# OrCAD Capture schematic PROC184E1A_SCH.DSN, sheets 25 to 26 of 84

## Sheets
25 24. SOC ANALOG POWER 1: size C; title: SOC ANALOG POWER 1; company: TEXAS INSTRUMENTS INCORPORATED; note: PROC184_SCH
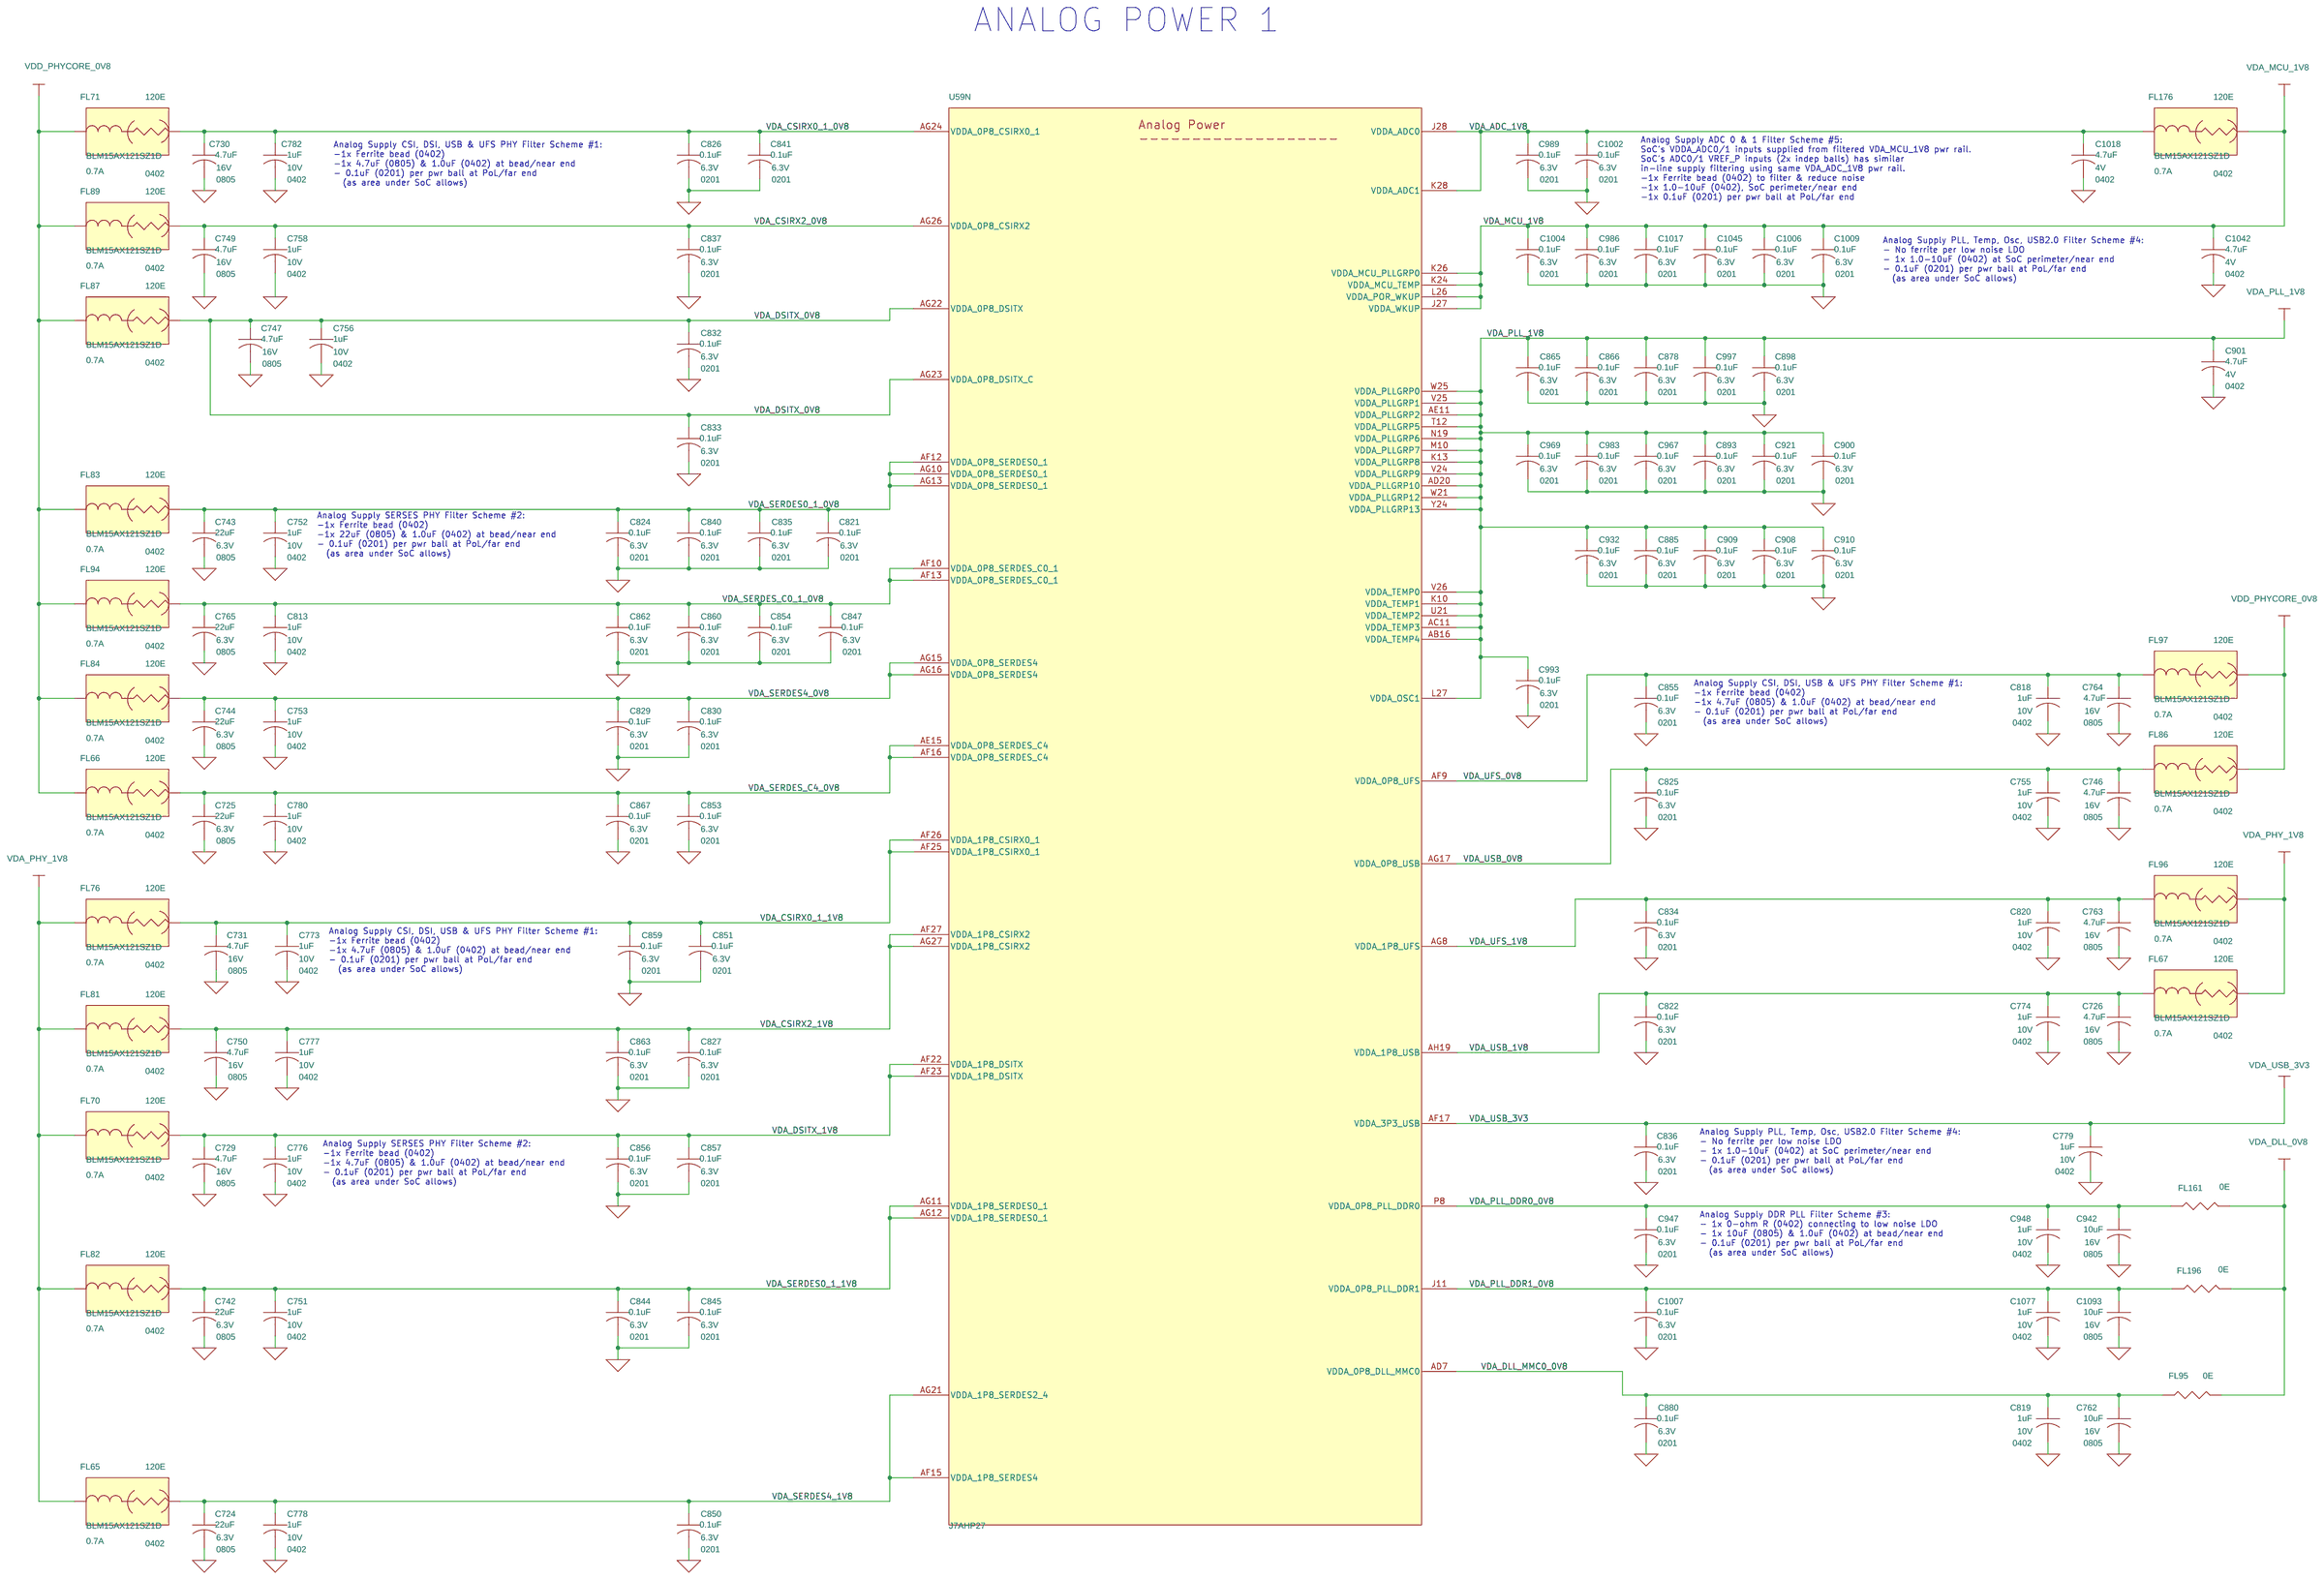
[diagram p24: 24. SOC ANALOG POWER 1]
26 25. SOC IO & SUPPORT POWER 2: size C; title: SOC DIGITAL IO & SUPPORT POWER 2; company: TEXAS INSTRUMENTS INCORPORATED; note: PROC184_SCH
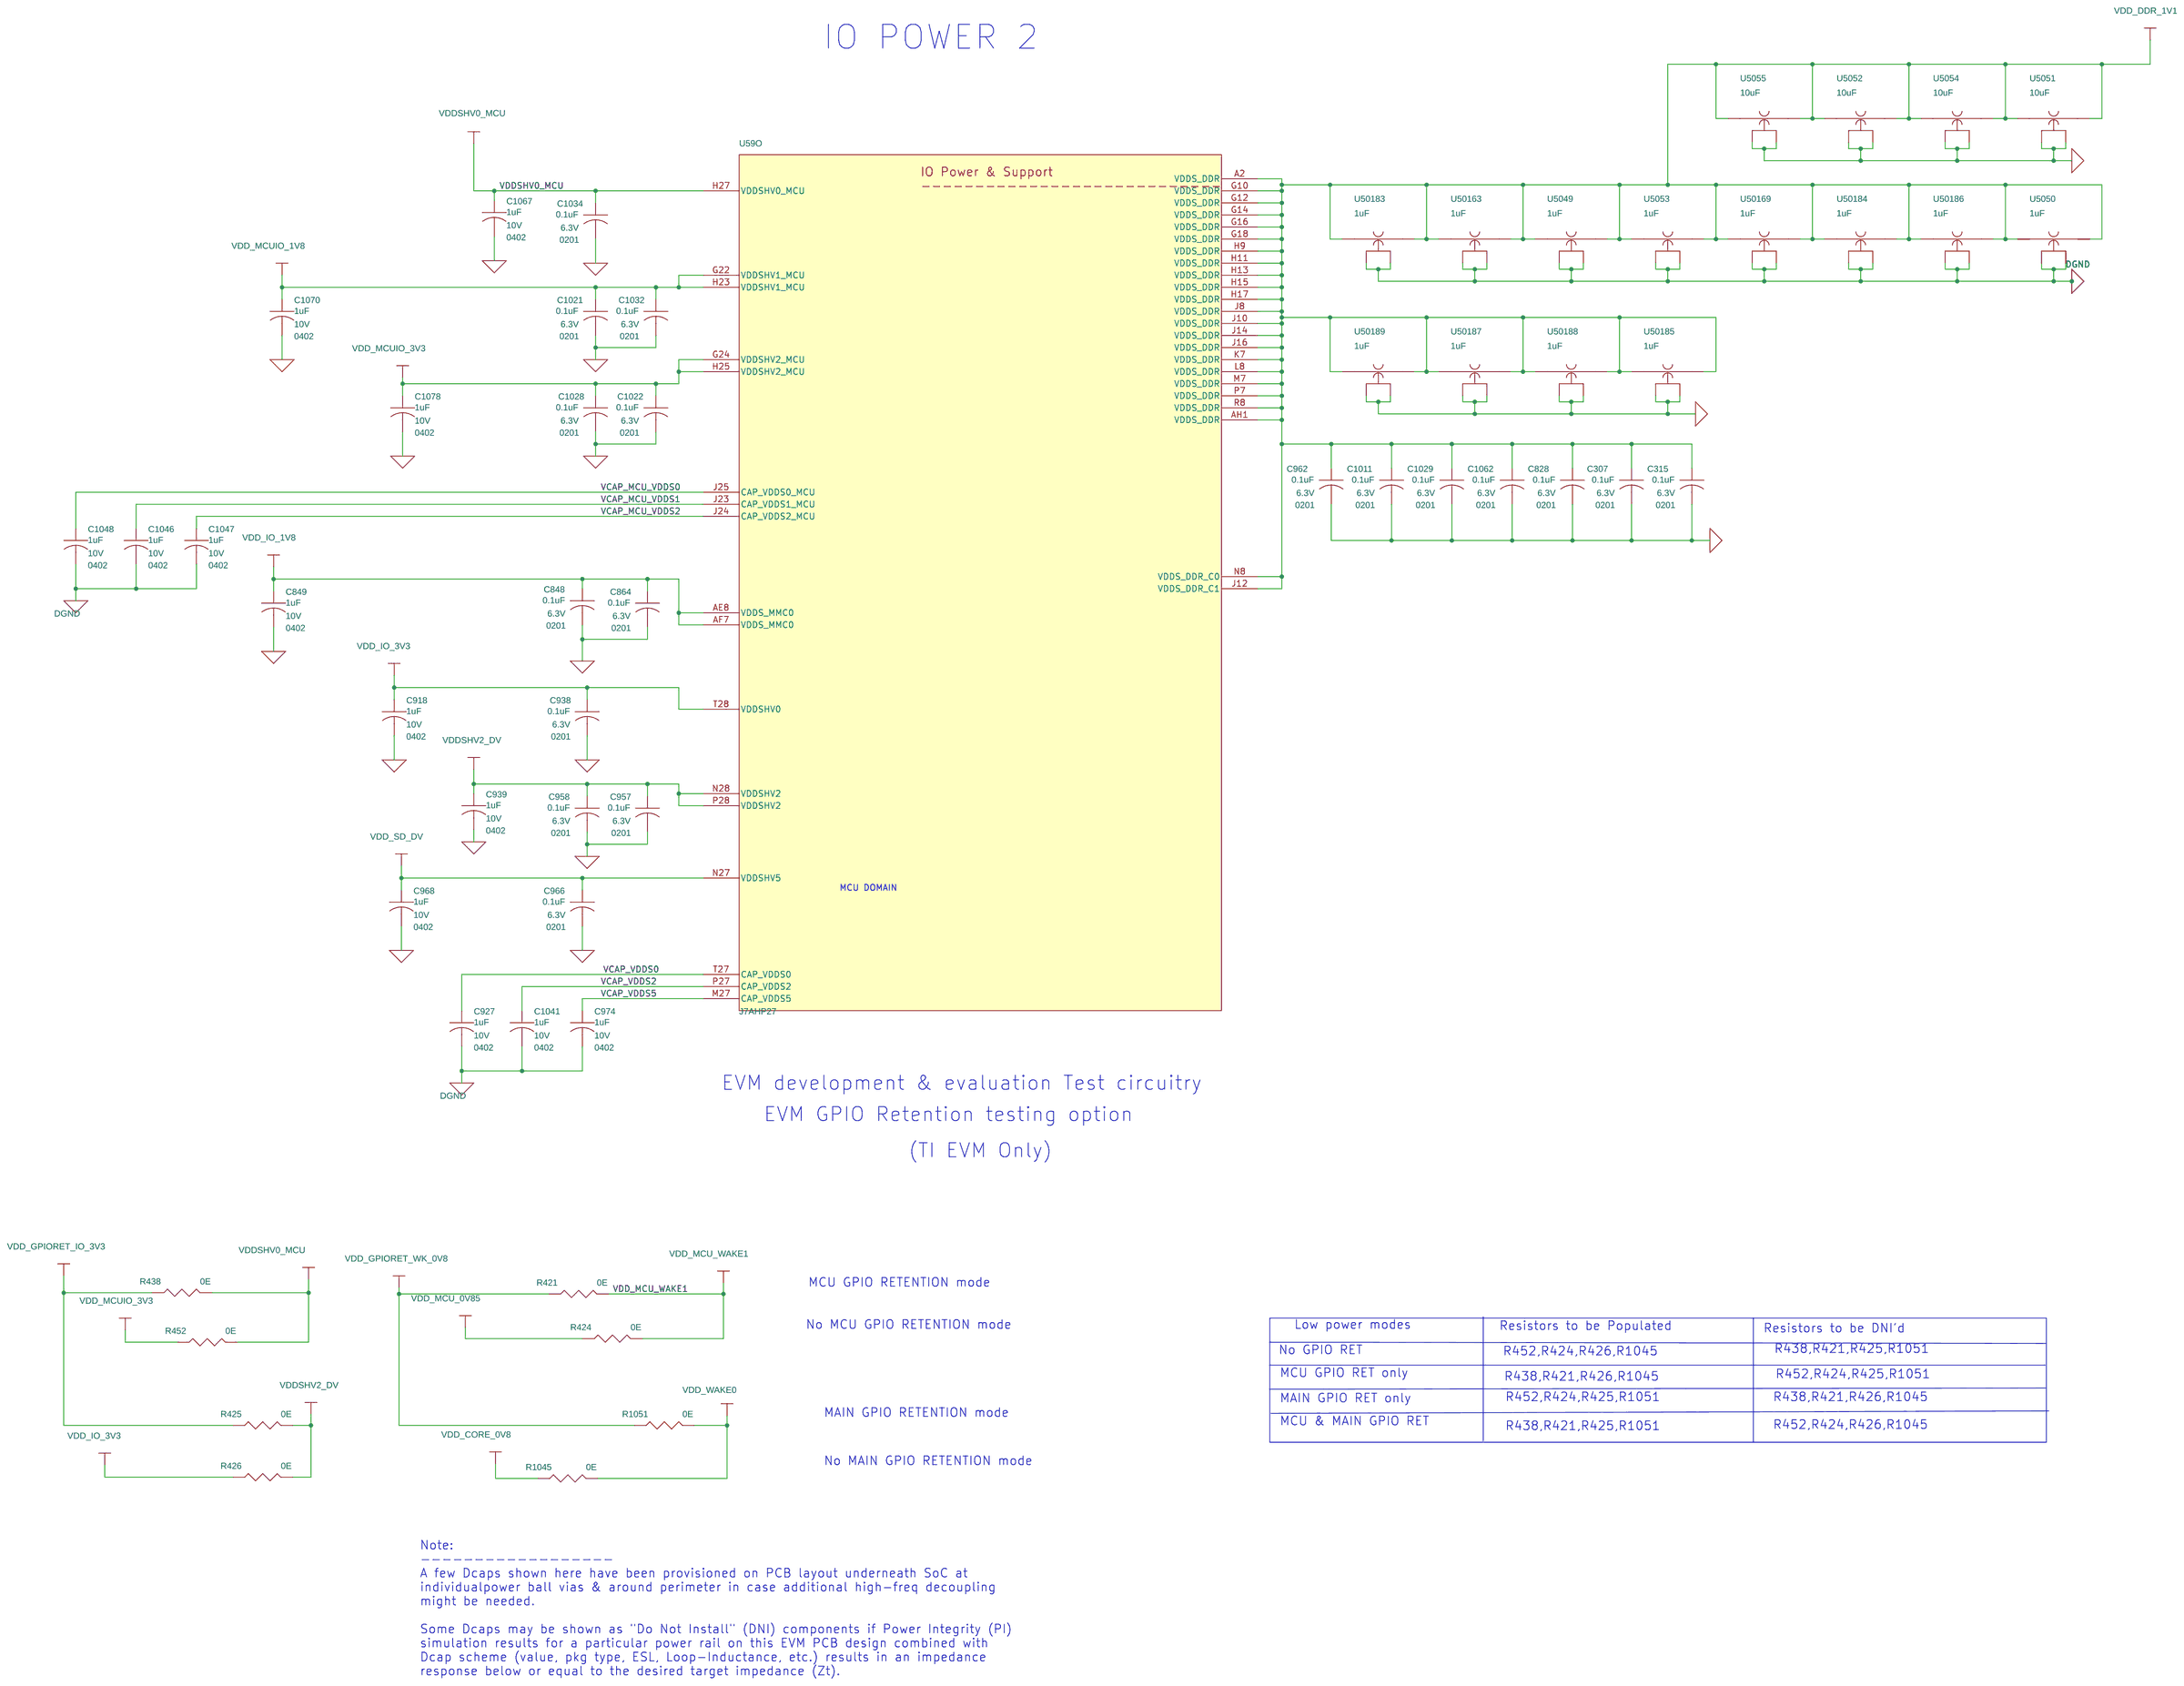
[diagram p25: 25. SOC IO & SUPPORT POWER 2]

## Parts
sheet 15. SOC EMIF1 & LPDDR4
U59  J7AHP27  [BGASKT-33X33-1063-P8MM]  (sections A,B,C,D,E,F,G,H,I,J,K,L,M,N,O,P,Q,R,S,T,U,V,W)
sheet 24. SOC ANALOG POWER 1
C724  22uF  [CAP0805_1-25]
C725  22uF  [CAP0805_1-25]
C726  4.7uF  [CAP0805_1-5]
C729  4.7uF  [CAP0805_1-5]
C730  4.7uF  [CAP0805_1-5]
C731  4.7uF  [CAP0805_1-5]
C742  22uF  [CAP0805_1-25]
C743  22uF  [CAP0805_1-25]
C744  22uF  [CAP0805_1-25]
C746  4.7uF  [CAP0805_1-5]
C747  4.7uF  [CAP0805_1-5]
C749  4.7uF  [CAP0805_1-5]
C750  4.7uF  [CAP0805_1-5]
C751  1uF  [CAP0402_0-75]
C752  1uF  [CAP0402_0-75]
C753  1uF  [CAP0402_0-75]
C755  1uF  [CAP0402_0-75]
C756  1uF  [CAP0402_0-75]
C758  1uF  [CAP0402_0-75]
C762  10uF  [CAP0805_1-5]
C763  4.7uF  [CAP0805_1-5]
C764  4.7uF  [CAP0805_1-5]
C765  22uF  [CAP0805_1-25]
C773  1uF  [CAP0402_0-75]
C774  1uF  [CAP0402_0-75]
C776  1uF  [CAP0402_0-75]
C777  1uF  [CAP0402_0-75]
C778  1uF  [CAP0402_0-75]
C779  1uF  [CAP0402_0-75]
C780  1uF  [CAP0402_0-75]
C782  1uF  [CAP0402_0-75]
C813  1uF  [CAP0402_0-75]
C818  1uF  [CAP0402_0-75]
C819  1uF  [CAP0402_0-75]
C820  1uF  [CAP0402_0-75]
C821  0.1uF  [CAP0201_0-5]
C822  0.1uF  [CAP0201_0-5]
C824  0.1uF  [CAP0201_0-5]
C825  0.1uF  [CAP0201_0-5]
C826  0.1uF  [CAP0201_0-5]
C827  0.1uF  [CAP0201_0-5]
C829  0.1uF  [CAP0201_0-5]
C830  0.1uF  [CAP0201_0-5]
C832  0.1uF  [CAP0201_0-5]
C833  0.1uF  [CAP0201_0-5]
C834  0.1uF  [CAP0201_0-5]
C835  0.1uF  [CAP0201_0-5]
C836  0.1uF  [CAP0201_0-5]
C837  0.1uF  [CAP0201_0-5]
C840  0.1uF  [CAP0201_0-5]
C841  0.1uF  [CAP0201_0-5]
C844  0.1uF  [CAP0201_0-5]
C845  0.1uF  [CAP0201_0-5]
C847  0.1uF  [CAP0201_0-5]
C850  0.1uF  [CAP0201_0-5]
C851  0.1uF  [CAP0201_0-5]
C853  0.1uF  [CAP0201_0-5]
C854  0.1uF  [CAP0201_0-5]
C855  0.1uF  [CAP0201_0-5]
C856  0.1uF  [CAP0201_0-5]
C857  0.1uF  [CAP0201_0-5]
C859  0.1uF  [CAP0201_0-5]
C860  0.1uF  [CAP0201_0-5]
C862  0.1uF  [CAP0201_0-5]
C863  0.1uF  [CAP0201_0-5]
C865  0.1uF  [CAP0201_0-5]
C866  0.1uF  [CAP0201_0-5]
C867  0.1uF  [CAP0201_0-5]
C878  0.1uF  [CAP0201_0-5]
C880  0.1uF  [CAP0201_0-5]
C885  0.1uF  [CAP0201_0-5]
C893  0.1uF  [CAP0201_0-5]
C898  0.1uF  [CAP0201_0-5]
C900  0.1uF  [CAP0201_0-5]
C901  4.7uF  [CAP0402_0-75]
C908  0.1uF  [CAP0201_0-5]
C909  0.1uF  [CAP0201_0-5]
C910  0.1uF  [CAP0201_0-5]
C921  0.1uF  [CAP0201_0-5]
C932  0.1uF  [CAP0201_0-5]
C942  10uF  [CAP0805_1-5]
C947  0.1uF  [CAP0201_0-5]
C948  1uF  [CAP0402_0-75]
C967  0.1uF  [CAP0201_0-5]
C969  0.1uF  [CAP0201_0-5]
C983  0.1uF  [CAP0201_0-5]
C986  0.1uF  [CAP0201_0-5]
C989  0.1uF  [CAP0201_0-5]
C993  0.1uF  [CAP0201_0-5]
C997  0.1uF  [CAP0201_0-5]
C1002  0.1uF  [CAP0201_0-5]
C1004  0.1uF  [CAP0201_0-5]
C1006  0.1uF  [CAP0201_0-5]
C1007  0.1uF  [CAP0201_0-5]
C1009  0.1uF  [CAP0201_0-5]
C1017  0.1uF  [CAP0201_0-5]
C1018  4.7uF  [CAP0402_0-75]
C1042  4.7uF  [CAP0402_0-75]
C1045  0.1uF  [CAP0201_0-5]
C1077  1uF  [CAP0402_0-75]
C1093  10uF  [CAP0805_1-5]
FL65  120E  [EMIFIL_BLM15A_0402_0-6]
FL66  120E  [EMIFIL_BLM15A_0402_0-6]
FL67  120E  [EMIFIL_BLM15A_0402_0-6]
FL70  120E  [EMIFIL_BLM15A_0402_0-6]
FL71  120E  [EMIFIL_BLM15A_0402_0-6]
FL76  120E  [EMIFIL_BLM15A_0402_0-6]
FL81  120E  [EMIFIL_BLM15A_0402_0-6]
FL82  120E  [EMIFIL_BLM15A_0402_0-6]
FL83  120E  [EMIFIL_BLM15A_0402_0-6]
FL84  120E  [EMIFIL_BLM15A_0402_0-6]
FL86  120E  [EMIFIL_BLM15A_0402_0-6]
FL87  120E  [EMIFIL_BLM15A_0402_0-6]
FL89  120E  [EMIFIL_BLM15A_0402_0-6]
FL94  120E  [EMIFIL_BLM15A_0402_0-6]
FL95  0E  [RES0402_0-5]
FL96  120E  [EMIFIL_BLM15A_0402_0-6]
FL97  120E  [EMIFIL_BLM15A_0402_0-6]
FL161  0E  [RES0402_0-5]
FL176  120E  [EMIFIL_BLM15A_0402_0-6]
FL196  0E  [RES0402_0-5]
sheet 25. SOC IO & SUPPORT POWER 2
C307  0.1uF  [CAP0201_0-5]
C315  0.1uF  [CAP0201_0-5]
C828  0.1uF  [CAP0201_0-5]
C848  0.1uF  [CAP0201_0-5]
C849  1uF  [CAP0402_0-75]
C864  0.1uF  [CAP0201_0-5]
C918  1uF  [CAP0402_0-75]
C927  1uF  [CAP0402_0-75]
C938  0.1uF  [CAP0201_0-5]
C939  1uF  [CAP0402_0-75]
C957  0.1uF  [CAP0201_0-5]
C958  0.1uF  [CAP0201_0-5]
C962  0.1uF  [CAP0201_0-5]
C966  0.1uF  [CAP0201_0-5]
C968  1uF  [CAP0402_0-75]
C974  1uF  [CAP0402_0-75]
C1011  0.1uF  [CAP0201_0-5]
C1021  0.1uF  [CAP0201_0-5]
C1022  0.1uF  [CAP0201_0-5]
C1028  0.1uF  [CAP0201_0-5]
C1029  0.1uF  [CAP0201_0-5]
C1032  0.1uF  [CAP0201_0-5]
C1034  0.1uF  [CAP0201_0-5]
C1041  1uF  [CAP0402_0-75]
C1046  1uF  [CAP0402_0-75]
C1047  1uF  [CAP0402_0-75]
C1048  1uF  [CAP0402_0-75]
C1062  0.1uF  [CAP0201_0-5]
C1067  1uF  [CAP0402_0-75]
C1070  1uF  [CAP0402_0-75]
C1078  1uF  [CAP0402_0-75]
R421  0E  [RES0402_0-5]
R424  0E  [RES0402_0-5]
R425  0E  [RES0402_0-5]
R426  0E  [RES0402_0-5]
R438  0E  [RES0402_0-5]
R452  0E  [RES0402_0-5]
R1045  0E  [RES0402_0-5]
R1051  0E  [RES0402_0-5]
U5049  1uF  [EMIFIL_NFM15CC_0402_0-5_TI]
U5050  1uF  [EMIFIL_NFM15CC_0402_0-5_TI]
U5051  10uF  [EMIFIL_NFM18C_0603_0-7_TI]
U5052  10uF  [EMIFIL_NFM18C_0603_0-7_TI]
U5053  1uF  [EMIFIL_NFM15CC_0402_0-5_TI]
U5054  10uF  [EMIFIL_NFM18C_0603_0-7_TI]
U5055  10uF  [EMIFIL_NFM18C_0603_0-7_TI]
U50163  1uF  [EMIFIL_NFM15CC_0402_0-5_TI]
U50169  1uF  [EMIFIL_NFM15CC_0402_0-5_TI]
U50183  1uF  [EMIFIL_NFM15CC_0402_0-5_TI]
U50184  1uF  [EMIFIL_NFM15CC_0402_0-5_TI]
U50185  1uF  [EMIFIL_NFM15CC_0402_0-5_TI]
U50186  1uF  [EMIFIL_NFM15CC_0402_0-5_TI]
U50187  1uF  [EMIFIL_NFM15CC_0402_0-5_TI]
U50188  1uF  [EMIFIL_NFM15CC_0402_0-5_TI]
U50189  1uF  [EMIFIL_NFM15CC_0402_0-5_TI]

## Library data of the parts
U59 = J7AHP27SoC_BGA1063: IC J7AHP27 SoC EVM MICROPROCESSOR BGA1063; Chkd/date: PRADEEP/181223; Crtd /date: TAMILARASU/111223; Custom_Duty: 15%; Customs_HS_Code: 85423100; Distributor_name: NA; Distributor_part_number: NA; Footprint Path: Y:\MIS_DATABASE\Library\ALTIUM_TOOL\PCB_FOOTPRINTS\Altium_Footprint_Lib.PcbLib; Height: 3.30MM; Library Path: Y:\MIS_DATABASE\Library\ALTIUM_TOOL\SCHEMATICS_PARTS\MS_MICROPROCESSOR_Library.schlib; Mfr_name: NA; Mistral Part No: 141223120002; Package: BGA1063; Part_type: ICS\DIGITAL\MICROPROCESSOR; Project: J7AHP27_V08 SOC; RoHS: NA; Temperature: NA; Tolerance: NA; Voltage: NA; Wattage: NA; Weight: NA; Datasheet: Y:\MIS_DATABASE\DATASHEETS\ICS\DIGITAL\MICROCONTROLLER\J7AHP27.PDF
C724 C725 C742-C744 C765 = CAP: CAP CERAMIC 22uF 6.3V 20% X7T AUTO 0805; Automotive Alternate_mfr_name: TDK; Automotive Alternate_mfr_part_number: CGA4J1X7T0J226M; Chkd/date: MANIRAJA/261018; Crtd /date: ALVY/251018; Custom_Duty: 15%; Customs_HS_Code: 85322990; Distributor_name: MOUSER; Distributor_part_number: 81-GCM21BD70J226ME6L; Footprint Path: Y:\MIS_DATABASE\Library\ALTIUM_TOOL\PCB_FOOTPRINTS\Altium_Footprint_Lib.PcbLib; Height: 1.25MM; Library Path: Y:\MIS_DATABASE\Library\ALTIUM_TOOL\SCHEMATICS_PARTS\MS_DISCRETE_Library.schlib; Manufacturer: MURATA; Mfr_name: MURATA; Mfr_part_number: GCM21BD70J226ME36L; Mistral Part No: 120018100065-R; Package: 0805; Part_type: CAPACITORS\CERAMIC; Project: TI_J7ES_EVM_SOM; RoHS: RoHS; Temperature: -55°C+125°C; Tolerance: 20%; Voltage: 6.3V; Wattage: NA; Weight: NA; Datasheet: Y:\MIS_DATABASE\DATASHEETS\CAPACITORS\GCM-SERIES.PDF
C726 C729-C731 C746 C747 C749 C750 C763 C764 = CAP: CAP CERAMIC 4.7uF 16V 10% X7R AUTO 0805; Chkd/date: MANIRAJA/011018; Crtd /date: MANIRAJA/011018; Custom_Duty: 15%; Customs_HS_Code: 85322990; Distributor_name: DIGIKEY; Distributor_part_number: 490-14532-1-ND; Footprint Path: Y:\MIS_DATABASE\Library\ALTIUM_TOOL\PCB_FOOTPRINTS\Altium_Footprint_Lib.PcbLib; Footprint Ref: CAP0805_1-25; Height: 1.40MM; Library Path: Y:\MIS_DATABASE\Library\ALTIUM_TOOL\SCHEMATICS_PARTS\MS_DISCRETE_Library.schlib; Manufacturer: MURATA; Mfr_name: MURATA; Mfr_part_number: GCM21BR71C475KA73K; Mistral Part No: 120018100002-R; Package: 0805; Part_type: CAPACITORS\CERAMIC; Project: TI_J7_SVB-DUT; RoHS: RoHS; Temperature: -55°C+125°C; Tolerance: 10%; Voltage: 16V; Wattage: NA; Weight: 9.5mg; Datasheet: Y:\MIS_DATABASE\DATASHEETS\CAPACITORS\GCM21BR71C475KA73.PDF
C751-C753 C755 C756 C758 C773 C774 C776-C780 C782 C813 C818-C820 C849 C918 C927 C939 C948 C968 C974 C1041 C1046-C1048 C1067 C1070 C1077 C1078 = CAP: CAP CERAMIC 1uF 10V 10% X7S AUTO 0402; Chkd/date: MANIRAJA/100918; Crtd /date: ALVY/100918; Custom_Duty: 15%; Customs_HS_Code: 85322990; Distributor_name: DIGIKEY; Distributor_part_number: 490-13409-1-ND; Footprint Path: Y:\MIS_DATABASE\Library\ALTIUM_TOOL\PCB_FOOTPRINTS\Altium_Footprint_Lib.PcbLib; Height: 0.70MM; Library Path: Y:\MIS_DATABASE\Library\ALTIUM_TOOL\SCHEMATICS_PARTS\MS_DISCRETE_Library.schlib; Manufacturer: MURATA; Mfr_name: MURATA; Mfr_part_number: GCM155C71A105KE38D; Mistral Part No: 120018090021-R; Package: 0402; Part_type: CAPACITORS\CERAMIC; Project: SMART-M_SCRIPTALK_PB; RoHS: RoHS; Temperature: -55°C+125°C; Tolerance: 10%; Voltage: 10V; Wattage: NA; Weight: 6mg; Datasheet: Y:\MIS_DATABASE\DATASHEETS\CAPACITORS\MURATA-GCM-SER.PDF
C762 C942 C1093 = CAP: CAP CERAMIC 10uF 16V 10% X7S AUTO 0805; Automotive Alternate_mfr_name: TDK; Automotive Alternate_mfr_part_number: CGA4J1X7S1C106K125AC; Chkd/date: MANIRAJA/181120; Crtd /date: ALVY/171120; Custom_Duty: 15%; Customs_HS_Code: 85322990; Direct Alternate_mfr_name: TDK; Direct Alternate_mfr_part_number: C2012X7S1C106K125AC; Distributor_name: DIGIKEY; Distributor_part_number: 490-GCM21BC71C106KE36KTR-ND; Footprint Path: Y:\MIS_DATABASE\Library\ALTIUM_TOOL\PCB_FOOTPRINTS\Altium_Footprint_Lib.PcbLib; Height: 1.45MM; Library Path: Y:\MIS_DATABASE\Library\ALTIUM_TOOL\SCHEMATICS_PARTS\MS_DISCRETE_Library.schlib; Manufacturer: MURATA; Mfr_name: MURATA; Mfr_part_number: GCM21BC71C106KE36K; Mistral Part No: 120020110016-R; Package: 0805; Part_type: CAPACITORS\CERAMIC; Project: J7_CP; RoHS: RoHS; Temperature: -55°C+125°C; Tolerance: 10%; Voltage: 16V; Wattage: NA; Weight: 34mg; Datasheet: Y:\MIS_DATABASE\DATASHEETS\CAPACITORS\MURATA-GCM-SER.PDF
C307 C821 C822 C825-C828 C830 C832-C837 C840 C841 C845 C847 C850 C851 C853-C857 C860 C862 C866 C867 C878 C880 C885 C893 C898 C900 C908-C910 C921 C947 C962 C967 C969 C983 C986 C989 C997 C1002 C1006 C1007 C1009 C1029 C1045 = CAP: CAP CERAMIC 0.1uF 6.3V 10% X7S AUTO 0201; Assembly_Instruction: DNI; Chkd/date: MANIRAJA/011018; Crtd /date: MANIRAJA/011018; Custom_Duty: 15%; Customs_HS_Code: 85322990; Distributor_name: NA; Distributor_part_number: NA; Footprint Path: Y:\MIS_DATABASE\Library\ALTIUM_TOOL\PCB_FOOTPRINTS\Altium_Footprint_Lib.PcbLib; Height: 0.33MM; Library Path: Y:\MIS_DATABASE\Library\ALTIUM_TOOL\SCHEMATICS_PARTS\MS_DISCRETE_Library.schlib; Manufacturer: MURATA; Mfr_name: MURATA; Mfr_part_number: GCM033C70J104KE02D; Mistral Part No: 120018100001-R; Package: 0201; Part_type: CAPACITORS\CERAMIC; Project: TI_J7_SVB-DUT; RoHS: RoHS; Temperature: -55°C+125°C; Tolerance: 10%; Voltage: 6.3V; Wattage: NA; Weight: NA; Datasheet: Y:\MIS_DATABASE\DATASHEETS\CAPACITORS\MURATA-GCM-SER.PDF
C315 C824 C829 C844 C848 C859 C863-C865 C932 C938 C957 C958 C966 C993 C1004 C1011 C1017 C1021 C1022 C1028 C1032 C1034 C1062 = CAP: CAP CERAMIC 0.1uF 6.3V 10% X7S AUTO 0201; Chkd/date: MANIRAJA/011018; Crtd /date: MANIRAJA/011018; Custom_Duty: 15%; Customs_HS_Code: 85322990; Distributor_name: NA; Distributor_part_number: NA; Footprint Path: Y:\MIS_DATABASE\Library\ALTIUM_TOOL\PCB_FOOTPRINTS\Altium_Footprint_Lib.PcbLib; Height: 0.33MM; Library Path: Y:\MIS_DATABASE\Library\ALTIUM_TOOL\SCHEMATICS_PARTS\MS_DISCRETE_Library.schlib; Manufacturer: MURATA; Mfr_name: MURATA; Mfr_part_number: GCM033C70J104KE02D; Mistral Part No: 120018100001-R; Package: 0201; Part_type: CAPACITORS\CERAMIC; Project: TI_J7_SVB-DUT; RoHS: RoHS; Temperature: -55°C+125°C; Tolerance: 10%; Voltage: 6.3V; Wattage: NA; Weight: NA; Datasheet: Y:\MIS_DATABASE\DATASHEETS\CAPACITORS\MURATA-GCM-SER.PDF
C901 C1018 C1042 = CAP: CAP CERAMIC 4.7uF 4V 20% X7T 0402; Chkd/date: PRAVEEN/130922; Crtd /date: PRAVEEN/130922; Custom_Duty: 15%; Customs_HS_Code: 85322990; Distributor_name: NA; Distributor_part_number: NA; Footprint Path: Y:\MIS_DATABASE\Library\ALTIUM_TOOL\PCB_FOOTPRINTS\Altium_Footprint_Lib.PcbLib; Height: 0.70MM; Library Path: Y:\MIS_DATABASE\Library\ALTIUM_TOOL\SCHEMATICS_PARTS\MS_DISCRETE_Library.schlib; Manufacturer: MURATA; Mfr_name: MURATA; Mfr_part_number: GCM155D70G475ME36; Mistral Part No: 120022090013-R; Package: 0402; Part_type: CAPACITORS\CERAMIC; Project: J7AHP_EVM; RoHS: RoHS; Temperature: -55°C+125°C; Tolerance: 20%; Voltage: 4V; Wattage: NA; Weight: 1.6mg; Datasheet: Y:\MIS_DATABASE\DATASHEETS\CAPACITORS\GCM155D70G475ME36.PDF
FL65-FL67 FL70 FL71 FL76 FL81-FL84 FL86 FL87 FL89 FL94 FL96 FL97 FL176 = EMIFILTER_IND: IND FERRITE BEAD CHIP 120E 700mA 0402; Automotive Alternate_mfr_name: TDK; Automotive Alternate_mfr_part_number: MPZ1608S121ATDH5; Chkd/date: MANIRAJA/170122; Crtd /date: TAMILARASU/170122; Custom_Duty: 24%; Customs_HS_Code: 85437099; Direct Alternate_mfr_name: TDK; Direct Alternate_mfr_part_number: MPZ1608S121ATAH0; Distributor_name: DIGIKEY; Distributor_part_number: 490-16510-1-ND; Footprint Path: Y:\MIS_DATABASE\Library\ALTIUM_TOOL\PCB_FOOTPRINTS\Altium_Footprint_Lib.PcbLib; Height: 0.55MM; Library Path: Y:\MIS_DATABASE\Library\ALTIUM_TOOL\SCHEMATICS_PARTS\MS_FILTER_Library.schlib; Manufacturer: MURATA; Mfr_name: MURATA; Mfr_part_number: BLM15AX121SZ1D; Mistral Part No: 130022010017-R; Package: 0402; Part_type: INDUCTOR; Project: J7AHP_PROTO_BRD; RoHS: RoHS; SAT Current: 0.7A; Temperature: -55°C+125°C; Tolerance: 25%; Voltage: NA; Wattage: NA; Weight: 1mg; Datasheet: Y:\MIS_DATABASE\DATASHEETS\DISCRETES\INDUCTORS\BLM15-SZ1D-SER.PDF
FL95 FL161 FL196 = RESISTOR: RES 0E 1/10W JUMPER 0402; Chkd/date: VASANTHA/061216; Crtd /date: NAVEED/201014; Custom_Duty: 15%; Customs_HS_Code: 85332119; Distributor_name: DIGIKEY; Distributor_part_number: P0.0JCT-ND; Height: 0.40MM; Mfr_name: PANASONIC-ECG; Mfr_part_number: ERJ-2GE0R00X; Mistral Part No: 110018030052-R; Package: 0402; Part_type: RESISTORS\FIXED; Project: AEGIS POM; RoHS: RoHS; Temperature: -55°C+155°C; Tolerance: NA; Voltage: NA; Wattage: 1/10W; Weight: 0.8mg; Datasheet: Y:\MIS_DATABASE\DATASHEETS\RESISTORS\PAN-ERJSER_NOV17.PDF
R421 R424-R426 R438 R452 R1045 R1051 = RESISTOR: RES 0E 1/10W JUMPER 0402; Chkd/date: VASANTHA/061216; Crtd /date: NAVEED/201014; Custom_Duty: 15%; Customs_HS_Code: 85332119; Distributor_name: DIGIKEY; Distributor_part_number: P0.0JCT-ND; Footprint Path: Y:\MIS_DATABASE\Library\ALTIUM_TOOL\PCB_FOOTPRINTS\Altium_Footprint_Lib.PcbLib; Height: 0.40MM; IBISSP_MODLES: VALUE REPEATING 2 TIME; Library Path: Y:\MIS_DATABASE\Library\ALTIUM_TOOL\SCHEMATICS_PARTS\MS_DISCRETE_Library.schlib; Manufacturer: PANASONIC-ECG; Mfr_name: PANASONIC-ECG; Mfr_part_number: ERJ-2GE0R00X; Mistral Part No: 110018030052-R; Package: 0402; Part_type: RESISTORS\FIXED; Project: AEGIS POM; RoHS: RoHS; Temperature: -55°C+155°C; Tolerance: NA; Voltage: NA; Wattage: 1/10W; Weight: 0.8mg; Datasheet: Y:\MIS_DATABASE\DATASHEETS\RESISTORS\PAN-ERJSER_NOV17.PDF
U5049 U5050 U5053 U50163 U50169 U50183-U50189 = CAP_NFM_TI: PASSIVE FILTER EMI 1uF 4V AUTO 0402; Chkd/date: MANIRAJA/251018; Crtd /date: ALVY/251018; Custom_Duty: 15%; Customs_HS_Code: 85412900; Distributor_name: NA; Distributor_part_number: NA; Footprint Path: Y:\MIS_DATABASE\Library\ALTIUM_TOOL\PCB_FOOTPRINTS\Altium_Footprint_Lib.PcbLib; Height: 0.50MM; Library Path: Y:\MIS_DATABASE\Library\ALTIUM_TOOL\SCHEMATICS_PARTS\MS_FILTER_Library.schlib; Mfr_name: MURATA; Mfr_part_number: NFM15HC105D0G_TI; Mistral Part No: 130018100050; Package: 0402; Part_type: FILTER; Project: TI_J7ES_EVM_SOM; RoHS: NA; Temperature: NA; Tolerance: NA; Voltage: 4V; Wattage: NA; Weight: NA; Datasheet: Y:\MIS_DATABASE\DATASHEETS\DISCRETES\INDUCTORS\NFM15CC223C1A3.PDF
U5051 U5052 U5054 U5055 = CAP_NFM_TI: PASSIVE FILTER EMI 10uF 4V AUTO 0603; Chkd/date: MANIRAJA/251018; Crtd /date: ALVY/251018; Custom_Duty: 15%; Customs_HS_Code: 85412900; Distributor_name: NA; Distributor_part_number: NA; Footprint Path: Y:\MIS_DATABASE\Library\ALTIUM_TOOL\PCB_FOOTPRINTS\Altium_Footprint_Lib.PcbLib; Height: 0.70MM; Library Path: Y:\MIS_DATABASE\Library\ALTIUM_TOOL\SCHEMATICS_PARTS\MS_FILTER_Library.schlib; Mfr_name: MURATA; Mfr_part_number: NFM18HC106D0G_TI; Mistral Part No: 130018100049; Package: 0603; Part_type: FILTER; Project: TI_J7ES_EVM_SOM; RoHS: NA; Temperature: NA; Tolerance: NA; Voltage: 4V; Wattage: NA; Weight: NA; Datasheet: Y:\MIS_DATABASE\DATASHEETS\DISCRETES\INDUCTORS\NFM18HC-SER.PDF

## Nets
DGND: C307.2 C315.2 C724.2 C725.2 C726.2 C729.2 C730.2 C731.2 C742.2 C743.2 C744.2 C746.2 C747.2 C749.2 C750.2 C751.2 C752.2 C753.2 C755.2 C756.2 C758.2 C762.2 C763.2 C764.2 C765.2 C773.2 C774.2 C776.2 C777.2 C778.2 C779.2 C780.2 C782.2 C813.2 C818.2 C819.2 C820.2 C821.2 C822.2 C824.2 C825.2 C826.2 C827.2 C828.2 C829.2 C830.2 C832.2 C833.2 C834.2 C835.2 C836.2 C837.2 C840.2 C841.2 C844.2 C845.2 C847.2 C848.2 C849.2 C850.2 C851.2 C853.2 C854.2 C855.2 C856.2 C857.2 C859.2 C860.2 C862.2 C863.2 C864.2 C865.2 C866.2 C867.2 C878.2 C880.2 C885.2 C893.2 C898.2 C900.2 C901.2 C908.2 C909.2 C910.2 C918.2 C921.2 C927.2 C932.2 C938.2 C939.2 C942.2 C947.2 C948.2 C957.2 C958.2 C962.2 C966.2 C967.2 C968.2 C969.2 C974.2 C983.2 C986.2 C989.2 C993.2 C997.2 C1002.2 C1004.2 C1006.2 C1007.2 C1009.2 C1011.2 C1017.2 C1018.2 C1021.2 C1022.2 C1028.2 C1029.2 C1032.2 C1034.2 C1041.2 C1042.2 C1045.2 C1046.2 C1047.2 C1048.2 C1062.2 C1067.2 C1070.2 C1077.2 C1078.2 C1093.2 U5049.2 U5049.4 U5050.2 U5050.4 U5051.2 U5051.4 U5052.2 U5052.4 U5053.2 U5053.4 U5054.2 U5054.4 U5055.2 U5055.4 U50163.2 U50163.4 U50169.2 U50169.4 U50183.2 U50183.4 U50184.2 U50184.4 U50185.2 U50185.4 U50186.2 U50186.4 U50187.2 U50187.4 U50188.2 U50188.4 U50189.2 U50189.4 ; also on sheet 11 12 13 14 15 16 17 18 20 21 22 23 24 27 28 29 30 31 32 33 34 35 36 37 38 39 40 41 42 43 44 45 46 47 48 49 50 51 52 53 54 55 56 57 58 59 60 61 62 63 64 65 66 67 68 69 70 71 72 73 76 77 78 79 81 82 83 84
VDD_CORE_0V8: R1045.1 ; also on sheet 27 28 54 71 74
VDD_DDR_1V1: C307.1 C315.1 C828.1 C962.1 C1011.1 C1029.1 C1062.1 U59.A2(VDDS_DDR) U59.AH1(VDDS_DDR) U59.G10(VDDS_DDR) U59.G12(VDDS_DDR) U59.G14(VDDS_DDR) U59.G16(VDDS_DDR) U59.G18(VDDS_DDR) U59.H9(VDDS_DDR) U59.H11(VDDS_DDR) U59.H13(VDDS_DDR) U59.H15(VDDS_DDR) U59.H17(VDDS_DDR) U59.J8(VDDS_DDR) U59.J10(VDDS_DDR) U59.J12(VDDS_DDR_C1) U59.J14(VDDS_DDR) U59.J16(VDDS_DDR) U59.K7(VDDS_DDR) U59.L8(VDDS_DDR) U59.M7(VDDS_DDR) U59.N8(VDDS_DDR_C0) U59.P7(VDDS_DDR) U59.R8(VDDS_DDR) U5049.1 U5049.3 U5050.1 U5050.3 U5051.1 U5051.3 U5052.1 U5052.3 U5053.1 U5053.3 U5054.1 U5054.3 U5055.1 U5055.3 U50163.1 U50163.3 U50169.1 U50169.3 U50183.1 U50183.3 U50184.1 U50184.3 U50185.1 U50185.3 U50186.1 U50186.3 U50187.1 U50187.3 U50188.1 U50188.3 U50189.1 U50189.3 ; also on sheet 14 15 28 69 74 75
VDD_GPIORET_IO_3V3: R425.1 R438.1 ; also on sheet 54 69 74
VDD_GPIORET_WK_0V8: R421.1 R1051.1 ; also on sheet 54 74
VDD_IO_1V8: C848.1 C849.1 C864.1 U59.AE8(VDDS_MMC0) U59.AF7(VDDS_MMC0) ; also on sheet 69 72 74
VDD_IO_3V3: C918.1 C938.1 R426.1 U59.T28(VDDSHV0) ; also on sheet 54 72 74
VDD_MCU_0V85: R424.1 ; also on sheet 27 28 54 69 72 74
VDD_MCU_WAKE1: R421.2 R424.2 ; also on sheet 27
VDD_MCUIO_1V8: C1021.1 C1032.1 C1070.1 U59.G22(VDDSHV1_MCU) U59.H23(VDDSHV1_MCU) ; also on sheet 54 69 74
VDD_MCUIO_3V3: C1022.1 C1028.1 C1078.1 R452.1 U59.G24(VDDSHV2_MCU) U59.H25(VDDSHV2_MCU) ; also on sheet 54 72 74
VDD_PHYCORE_0V8: FL66.1 FL71.1 FL83.1 FL84.1 FL86.2 FL87.1 FL89.1 FL94.1 FL97.2 ; also on sheet 74
VDD_SD_DV: C966.1 C968.1 U59.N27(VDDSHV5) ; also on sheet 40 74
VDD_WAKE0: R1045.2 R1051.2 ; also on sheet 27
VDDSHV0_MCU: C1034.1 C1067.1 R438.2 R452.2 U59.H27(VDDSHV0_MCU)
VDDSHV2_DV: C939.1 C957.1 C958.1 R425.2 R426.2 U59.N28(VDDSHV2) U59.P28(VDDSHV2)
VCAP_MCU_VDDS0: C1048.1 U59.J25(CAP_VDDS0_MCU)
VCAP_MCU_VDDS1: C1046.1 U59.J23(CAP_VDDS1_MCU)
VCAP_MCU_VDDS2: C1047.1 U59.J24(CAP_VDDS2_MCU)
VCAP_VDDS0: C927.1 U59.T27(CAP_VDDS0)
VCAP_VDDS2: C1041.1 U59.P27(CAP_VDDS2)
VCAP_VDDS5: C974.1 U59.M27(CAP_VDDS5)
VDA_ADC_1V8: C989.1 C1002.1 C1018.1 FL176.1 U59.J28(VDDA_ADC0) U59.K28(VDDA_ADC1)
VDA_CSIRX0_1_0V8: C730.1 C782.1 C826.1 C841.1 FL71.2 U59.AG24(VDDA_0P8_CSIRX0_1)
VDA_CSIRX0_1_1V8: C731.1 C773.1 C851.1 C859.1 FL76.2 U59.AF25(VDDA_1P8_CSIRX0_1) U59.AF26(VDDA_1P8_CSIRX0_1)
VDA_CSIRX2_0V8: C749.1 C758.1 C837.1 FL89.2 U59.AG26(VDDA_0P8_CSIRX2)
VDA_CSIRX2_1V8: C750.1 C777.1 C827.1 C863.1 FL81.2 U59.AF27(VDDA_1P8_CSIRX2) U59.AG27(VDDA_1P8_CSIRX2)
VDA_DLL_0V8: FL95.2 FL161.2 FL196.2 ; also on sheet 70 74
VDA_DLL_MMC0_0V8: C762.1 C819.1 C880.1 FL95.1 U59.AD7(VDDA_0P8_DLL_MMC0)
VDA_DSITX_0V8: C747.1 C756.1 C832.1 C833.1 FL87.2 U59.AG22(VDDA_0P8_DSITX) U59.AG23(VDDA_0P8_DSITX_C)
VDA_DSITX_1V8: C729.1 C776.1 C856.1 C857.1 FL70.2 U59.AF22(VDDA_1P8_DSITX) U59.AF23(VDDA_1P8_DSITX)
VDA_MCU_1V8: C986.1 C1004.1 C1006.1 C1009.1 C1017.1 C1042.1 C1045.1 FL176.2 U59.J27(VDDA_WKUP) U59.K24(VDDA_MCU_TEMP) U59.K26(VDDA_MCU_PLLGRP0) U59.L26(VDDA_POR_WKUP) ; also on sheet 21 36 69 74
VDA_PHY_1V8: FL65.1 FL67.2 FL70.1 FL76.1 FL81.1 FL82.1 FL96.2 ; also on sheet 54 74
VDA_PLL_1V8: C865.1 C866.1 C878.1 C885.1 C893.1 C898.1 C900.1 C901.1 C908.1 C909.1 C910.1 C921.1 C932.1 C967.1 C969.1 C983.1 C993.1 C997.1 U59.AB16(VDDA_TEMP4) U59.AC11(VDDA_TEMP3) U59.AD20(VDDA_PLLGRP10) U59.AE11(VDDA_PLLGRP2) U59.K10(VDDA_TEMP1) U59.K13(VDDA_PLLGRP8) U59.L27(VDDA_OSC1) U59.M10(VDDA_PLLGRP7) U59.N19(VDDA_PLLGRP6) U59.T12(VDDA_PLLGRP5) U59.U21(VDDA_TEMP2) U59.V24(VDDA_PLLGRP9) U59.V25(VDDA_PLLGRP1) U59.V26(VDDA_TEMP0) U59.W21(VDDA_PLLGRP12) U59.W25(VDDA_PLLGRP0) U59.Y24(VDDA_PLLGRP13) ; also on sheet 54 74
VDA_PLL_DDR0_0V8: C942.1 C947.1 C948.1 FL161.1 U59.P8(VDDA_0P8_PLL_DDR0)
VDA_PLL_DDR1_0V8: C1007.1 C1077.1 C1093.1 FL196.1 U59.J11(VDDA_0P8_PLL_DDR1)
VDA_SERDES0_1_0V8: C743.1 C752.1 C821.1 C824.1 C835.1 C840.1 FL83.2 U59.AF12(VDDA_0P8_SERDES0_1) U59.AG10(VDDA_0P8_SERDES0_1) U59.AG13(VDDA_0P8_SERDES0_1)
VDA_SERDES0_1_1V8: C742.1 C751.1 C844.1 C845.1 FL82.2 U59.AG11(VDDA_1P8_SERDES0_1) U59.AG12(VDDA_1P8_SERDES0_1)
VDA_SERDES4_0V8: C744.1 C753.1 C829.1 C830.1 FL84.2 U59.AG15(VDDA_0P8_SERDES4) U59.AG16(VDDA_0P8_SERDES4)
VDA_SERDES4_1V8: C724.1 C778.1 C850.1 FL65.2 U59.AF15(VDDA_1P8_SERDES4) U59.AG21(VDDA_1P8_SERDES2_4)
VDA_SERDES_C0_1_0V8: C765.1 C813.1 C847.1 C854.1 C860.1 C862.1 FL94.2 U59.AF10(VDDA_0P8_SERDES_C0_1) U59.AF13(VDDA_0P8_SERDES_C0_1)
VDA_SERDES_C4_0V8: C725.1 C780.1 C853.1 C867.1 FL66.2 U59.AE15(VDDA_0P8_SERDES_C4) U59.AF16(VDDA_0P8_SERDES_C4)
VDA_UFS_0V8: C764.1 C818.1 C855.1 FL97.1 U59.AF9(VDDA_0P8_UFS)
VDA_UFS_1V8: C763.1 C820.1 C834.1 FL96.1 U59.AG8(VDDA_1P8_UFS)
VDA_USB_0V8: C746.1 C755.1 C825.1 FL86.1 U59.AG17(VDDA_0P8_USB)
VDA_USB_1V8: C726.1 C774.1 C822.1 FL67.1 U59.AH19(VDDA_1P8_USB)
VDA_USB_3V3: C779.1 C836.1 U59.AF17(VDDA_3P3_USB) ; also on sheet 74

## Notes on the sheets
sheet 25
- ANALOG POWER 1
- Analog Supply CSI, DSI, USB & UFS PHY Filter Scheme #1:
  -1x Ferrite bead (0402)
  -1x 4.7uF (0805) & 1.0uF (0402) at bead/near end
  - 0.1uF (0201) per pwr ball at PoL/far end
    (as area under SoC allows)
- Analog Supply ADC 0 & 1 Filter Scheme #5:
  SoC's VDDA_ADC0/1 inputs supplied from filtered VDA_MCU_1V8 pwr rail.
  SoC's ADC0/1 VREF_P inputs (2x indep balls) has similar
  in-line supply filtering using same VDA_ADC_1V8 pwr rail.
  -1x Ferrite bead (0402) to filter & reduce noise
  -1x 1.0-10uF (0402), SoC perimeter/near end
  -1x 0.1uF (0201) per pwr ball at PoL/far end
- Analog Supply PLL, Temp, Osc, USB2.0 Filter Scheme #4:
  - No ferrite per low noise LDO
  - 1x 1.0-10uF (0402) at SoC perimeter/near end
  - 0.1uF (0201) per pwr ball at PoL/far end
    (as area under SoC allows)
- Analog Supply SERSES PHY Filter Scheme #2:
  -1x Ferrite bead (0402)
  -1x 22uF (0805) & 1.0uF (0402) at bead/near end
  - 0.1uF (0201) per pwr ball at PoL/far end
    (as area under SoC allows)
- Analog Supply CSI, DSI, USB & UFS PHY Filter Scheme #1:
  -1x Ferrite bead (0402)
  -1x 4.7uF (0805) & 1.0uF (0402) at bead/near end
  - 0.1uF (0201) per pwr ball at PoL/far end
    (as area under SoC allows)
- Analog Supply CSI, DSI, USB & UFS PHY Filter Scheme #1:
  -1x Ferrite bead (0402)
  -1x 4.7uF (0805) & 1.0uF (0402) at bead/near end
  - 0.1uF (0201) per pwr ball at PoL/far end
    (as area under SoC allows)
- Analog Supply PLL, Temp, Osc, USB2.0 Filter Scheme #4:
  - No ferrite per low noise LDO
  - 1x 1.0-10uF (0402) at SoC perimeter/near end
  - 0.1uF (0201) per pwr ball at PoL/far end
    (as area under SoC allows)
- Analog Supply SERSES PHY Filter Scheme #2:
  -1x Ferrite bead (0402)
  -1x 4.7uF (0805) & 1.0uF (0402) at bead/near end
  - 0.1uF (0201) per pwr ball at PoL/far end
    (as area under SoC allows)
- Analog Supply DDR PLL Filter Scheme #3:
  - 1x 0-ohm R (0402) connecting to low noise LDO
  - 1x 10uF (0805) & 1.0uF (0402) at bead/near end
  - 0.1uF (0201) per pwr ball at PoL/far end
    (as area under SoC allows)
sheet 26
- IO POWER 2
- MCU DOMAIN
- EVM development & evaluation Test circuitry
- EVM GPIO Retention testing option
- (TI EVM Only)
- MCU GPIO RETENTION mode
- No MCU GPIO RETENTION mode
- Low power modes
- Resistors to be Populated
- Resistors to be DNI'd
- No GPIO RET
- R452,R424,R426,R1045
- R438,R421,R425,R1051
- MCU GPIO RET only
- R438,R421,R426,R1045
- R452,R424,R425,R1051
- MAIN GPIO RET only
- R452,R424,R425,R1051
- R438,R421,R426,R1045
- MAIN GPIO RETENTION mode
- MCU & MAIN GPIO RET
- R438,R421,R425,R1051
- R452,R424,R426,R1045
- No MAIN GPIO RETENTION mode
- Note:
  ------------------
  A few Dcaps shown here have been provisioned on PCB layout underneath SoC at
  individualpower ball vias & around perimeter in case additional high-freq decoupling
  might be needed.
  Some Dcaps may be shown as "Do Not Install" (DNI) components if Power Integrity (PI)
  simulation results for a particular power rail on this EVM PCB design combined with
  Dcap scheme (value, pkg type, ESL, Loop-Inductance, etc.) results in an impedance
  response below or equal to the desired target impedance (Zt).
